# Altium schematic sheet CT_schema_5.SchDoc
size 298 x 247 mm
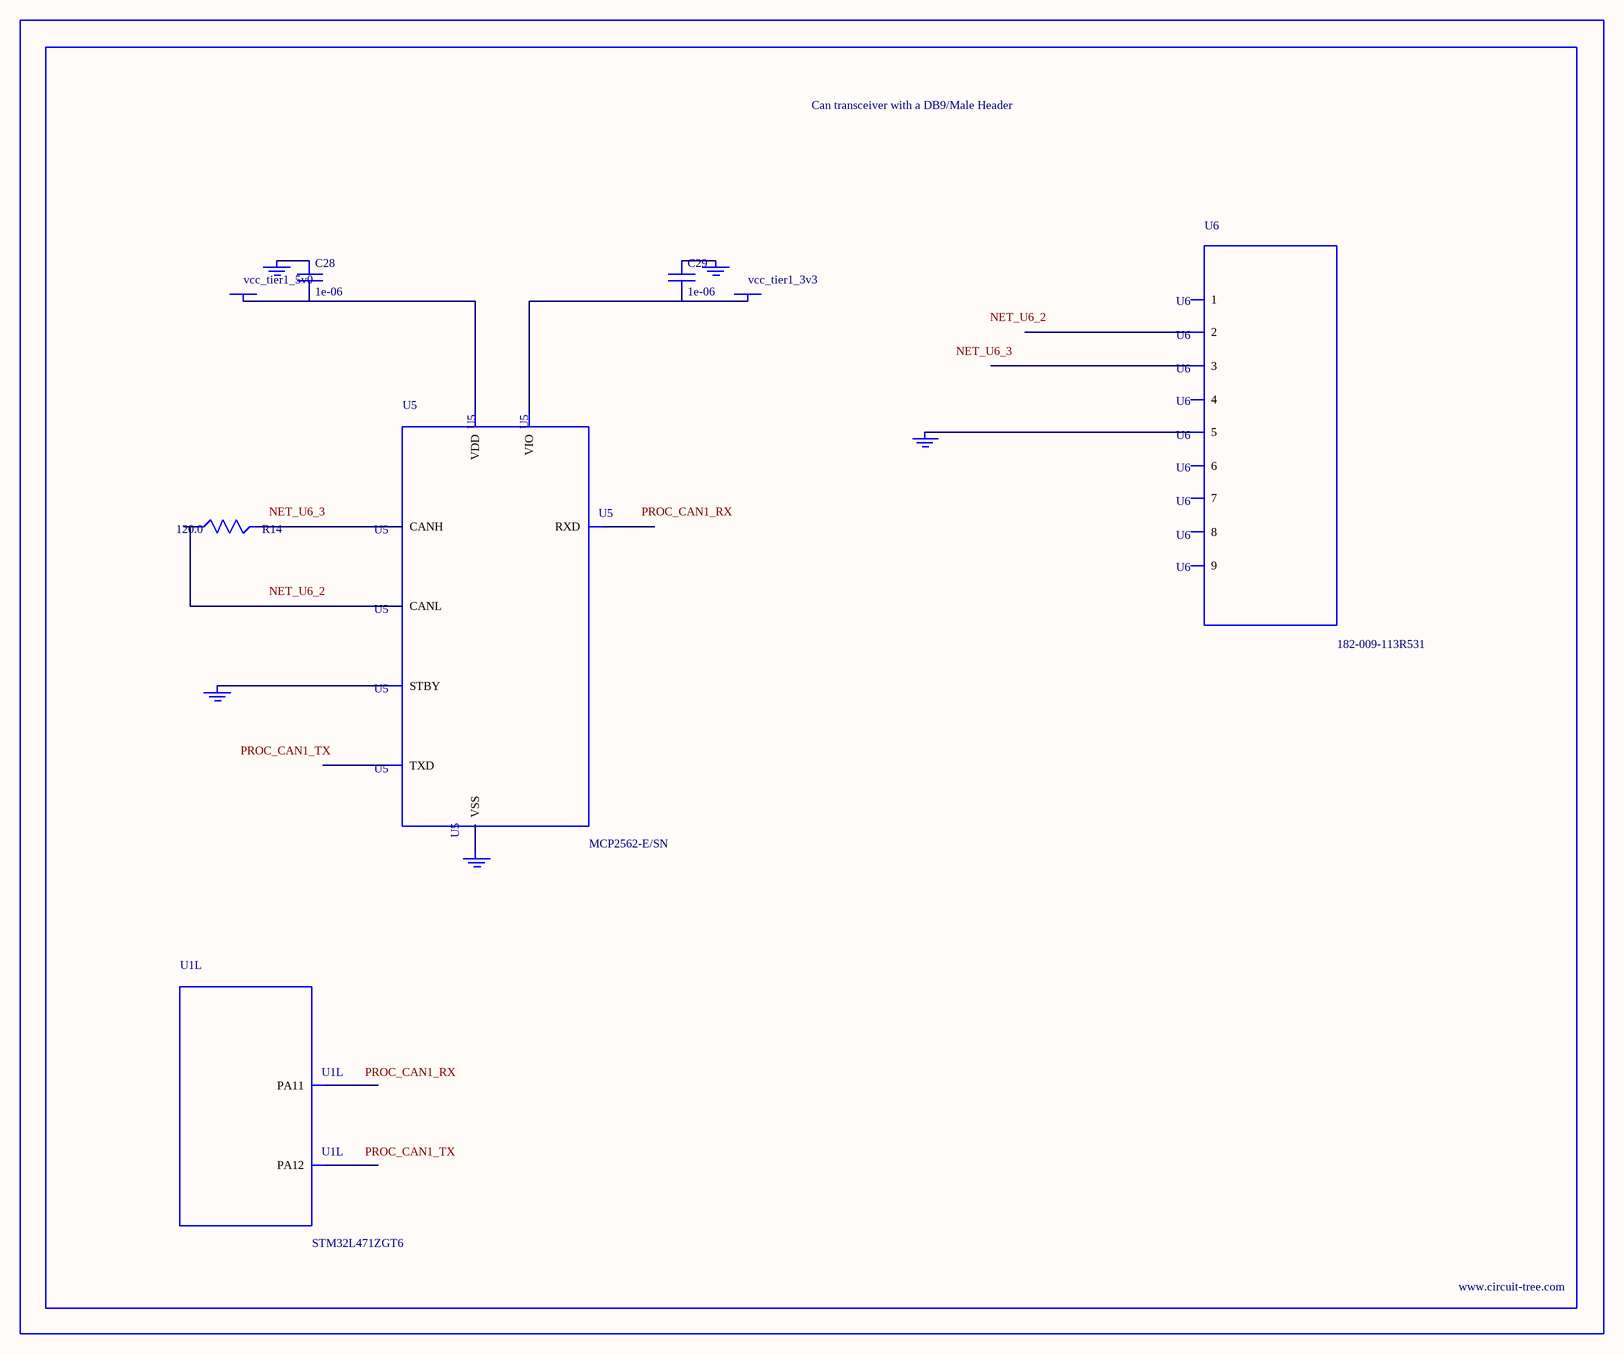
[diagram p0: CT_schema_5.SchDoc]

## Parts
BORDER4  (no value)
C28  1e-06  [C0603]
C29  1e-06  [C0603]
GND_INSTANCE_4_0  (no value)
GND_INSTANCE_4_1  (no value)
GND_INSTANCE_4_2  (no value)
GND_INSTANCE_4_3  (no value)
GND_INSTANCE_4_4  (no value)
POWER_INSTANCE_4_0  vcc_tier1_5v0
POWER_INSTANCE_4_1  vcc_tier1_3v3
R14  120.0  [R0603]
U1  STM32L471ZGT6  [LQFP144]  (part L of 14)
U5  MCP2562-E/SN  [SOIC-8]
U6  182-009-113R531  [182-009-MALE]

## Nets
NetC28_1: C28.1 GND_INSTANCE_4_0.0(GND)
NetC28_2: C28.2 POWER_INSTANCE_4_0.0(PWR) U5.3(VDD)
NetC29_1: C29.1 GND_INSTANCE_4_1.0(GND)
NetC29_2: C29.2 POWER_INSTANCE_4_1.0(PWR) U5.5(VIO)
NetGND_INSTANCE_4_2_0: GND_INSTANCE_4_2.0(GND) U5.8(STBY)
NetGND_INSTANCE_4_3_0: GND_INSTANCE_4_3.0(GND) U5.2(VSS)
NetGND_INSTANCE_4_4_0: GND_INSTANCE_4_4.0(GND) U6.5
NetR14_1: R14.1 U5.6(CANL)
NetR14_2: R14.2 U5.7(CANH)

Not connected (* = marked no-connect by the designer): U1 103(PA11) 104(PA12); U5 1(TXD) 4(RXD); U6 1 2 3 4 6 7 8 9

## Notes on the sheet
- Labels drawn without touching a wire or pin: NET_U6_2, NET_U6_3, PROC_CAN1_RX, PROC_CAN1_TX

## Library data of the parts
BORDER4 = BORDER_PAGE4
C28 C29 = C0603C105K3RACTU
GND_INSTANCE_4_0-GND_INSTANCE_4_4 = GND
POWER_INSTANCE_4_0 POWER_INSTANCE_4_1 = PWR
R14 = RC0603JR-07120RL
